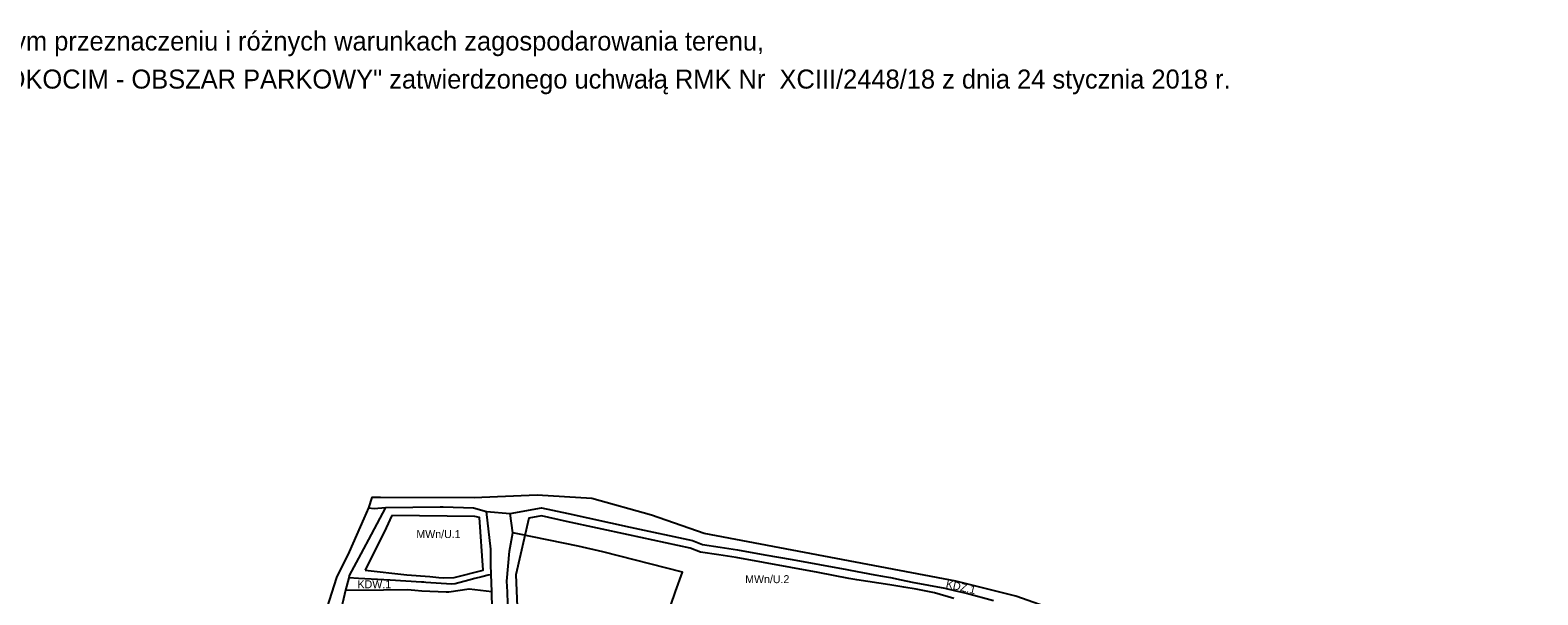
# Model space of a CAD drawing. Extents: x 7427219 to 7428976, y 5542673 to 5543767.
# Drawn here: x 7428025 to 7428976, y 5543411 to 5543767 of the extents above; entities that cross this region are included whole.
import ezdxf

# ---------------------------------------------------------------- set-up
doc = ezdxf.new("R2010")
doc.units = 0
for name, color, linetype in [('info', 7, 'Continuous'), ('linie rozgraniczające', 7, 'Continuous'), ('nieprzekraczalne linie zabudowy', 7, 'Continuous'), ('przeznaczenia terenów', 7, 'Continuous')]:
    doc.layers.add(name, color=color, linetype=linetype)

msp = doc.modelspace()

# ---------------------------------------------------------------- linework, layer by layer
at = {"layer": 'linie rozgraniczające'}
for points in [[(7428955.18, 5543269.67), (7428957.17, 5543269.08), (7428958.88, 5543268.54), (7428976.29, 5543277.15), (7428968.53, 5543280.57), (7428960.48, 5543282.86), (7428942.01, 5543289.47), (7428800.87, 5543352.36), (7428797.41, 5543343.78), (7428792.41, 5543346.08), (7428699.97, 5543390.65), (7428672.76, 5543400.83), (7428647, 5543409.84), (7428609.24, 5543419.25), (7428450.4, 5543449.31), (7428417.15, 5543461.01), (7428379.61, 5543471.46), (7428345.06, 5543473.61), (7428320.11, 5543472.52), (7428305.29, 5543471.75), (7428246.28, 5543471.97), (7428240.89, 5543471.99), (7428238.59, 5543465.57)], [(7428238.59, 5543465.57), (7428235.77, 5543458.71), (7428226.52, 5543437.77), (7428218.51, 5543421.58), (7428212.42, 5543402.38), (7428207.49, 5543383.26), (7428202.68, 5543363.59), (7428201.56, 5543343.87), (7428200.64, 5543323.96), (7428195.5, 5543304.35), (7428194.6, 5543302.15), (7428192.06, 5543294.17), (7428191.09, 5543292), (7428191.23, 5543284.94), (7428191.84, 5543269.96), (7428192.23, 5543264.28), (7428193.91, 5543244.78), (7428194.56, 5543235.45), (7428190.78, 5543234.89), (7428194.45, 5543220.26)], [(7428249.39, 5543465.75), (7428240.39, 5543448.79), (7428233.79, 5543436.58), (7428226.41, 5543422.9), (7428226.33, 5543421.38)], [(7428238.59, 5543465.57), (7428242.19, 5543465.16), (7428249.39, 5543465.75)], [(7428249.39, 5543465.75), (7428283.84, 5543466.14), (7428285.71, 5543466.08), (7428304.82, 5543465.56), (7428313.2, 5543463.31)], [(7428313.2, 5543463.31), (7428328.1, 5543461.86)], [(7428316.03, 5543423.42), (7428315.76, 5543429.79), (7428315.9, 5543438.71), (7428315.92, 5543439.4), (7428313.2, 5543463.31)], [(7428328.1, 5543461.86), (7428347.87, 5543465.51), (7428364.61, 5543461.88), (7428403.83, 5543453.36), (7428443.06, 5543444.83), (7428449.39, 5543442.51), (7428460.45, 5543440.81), (7428471.5, 5543439.11), (7428488.71, 5543435.99), (7428505.93, 5543432.86), (7428523.15, 5543429.74), (7428540.37, 5543426.61), (7428542.42, 5543426.2), (7428550.27, 5543424.76), (7428558.11, 5543423.32), (7428563, 5543422.45), (7428567.88, 5543421.58), (7428574.75, 5543420.12), (7428581.61, 5543418.65), (7428602.14, 5543414.85), (7428609.07, 5543413.25), (7428616, 5543411.66), (7428632.9, 5543406.99)], [(7428329.67, 5543449.79), (7428328.1, 5543461.86)], [(7428321.94, 5543244.46), (7428323.04, 5543250.26), (7428323.58, 5543267.97), (7428324.39, 5543280.12), (7428324.8, 5543286.26), (7428324.9, 5543291.59), (7428325.18, 5543294.57), (7428326.3, 5543306.46), (7428326.5, 5543316.1), (7428327.45, 5543338.07), (7428327.66, 5543360.9), (7428328.46, 5543379.09), (7428327.48, 5543394.39), (7428327.29, 5543397.44), (7428326.66, 5543404.98), (7428326.33, 5543412.61), (7428326.05, 5543419.3), (7428327.63, 5543438.11), (7428329.67, 5543449.79)], [(7428424.62, 5543379.08), (7428421.31, 5543380.22), (7428423.65, 5543387.36), (7428426.35, 5543395.61), (7428432.35, 5543412.79), (7428436.73, 5543424.89), (7428386.45, 5543437.69), (7428371, 5543441.36), (7428332.9, 5543449.13), (7428329.67, 5543449.79)], [(7428226.33, 5543421.38), (7428224.13, 5543413.63)], [(7428316.03, 5543423.42), (7428315.69, 5543423.33), (7428314.23, 5543422.97), (7428310.08, 5543421.94), (7428305.85, 5543420.89), (7428301.89, 5543419.85), (7428293.31, 5543417.59), (7428290.95, 5543417.38), (7428274.96, 5543418.45), (7428273.61, 5543418.6), (7428272.2, 5543418.75), (7428252.26, 5543419.89), (7428232.32, 5543421.03), (7428226.33, 5543421.38)], [(7428316.48, 5543412.76), (7428316.03, 5543423.42)], [(7428224.13, 5543413.63), (7428220.2, 5543396.4), (7428218.9, 5543395.88), (7428212.9, 5543375.79), (7428210.05, 5543366.97), (7428208.01, 5543350.56), (7428210.59, 5543325.44), (7428211.45, 5543313.62)], [(7428224.13, 5543413.63), (7428248.11, 5543413.83), (7428263.25, 5543414.07), (7428268, 5543413.51), (7428272.28, 5543413.15), (7428287.6, 5543412.55), (7428289.31, 5543412.48), (7428302.23, 5543414.39), (7428316.48, 5543412.76)], [(7428317.48, 5543350.67), (7428317.01, 5543369.34), (7428316.88, 5543379.9), (7428316.75, 5543390.46), (7428316.62, 5543401.61), (7428316.48, 5543412.76)]]:
    msp.add_lwpolyline(points, dxfattribs=at)
at = {"layer": 'nieprzekraczalne linie zabudowy'}
for points in [[(7428253.4, 5543460.61), (7428249.86, 5543452.95), (7428236.66, 5543426.14)], [(7428236.66, 5543426.14), (7428262.9, 5543423.24), (7428277.42, 5543422.14), (7428282.99, 5543421.51), (7428285.84, 5543421.45), (7428292.63, 5543421.5), (7428310.99, 5543426.24), (7428308.62, 5543459.36), (7428305.71, 5543460.14), (7428253.4, 5543460.61)], [(7428607.95, 5543408.38), (7428595.68, 5543411.9), (7428584.13, 5543414.23), (7428576.36, 5543415.49), (7428567.56, 5543416.93), (7428546.77, 5543420.14), (7428541.59, 5543421), (7428522.26, 5543424.82), (7428505.04, 5543427.94), (7428487.82, 5543431.07), (7428470.67, 5543434.18), (7428459.69, 5543435.87), (7428448.14, 5543437.64), (7428441.66, 5543440.02), (7428402.77, 5543448.47), (7428363.55, 5543456.99), (7428347.79, 5543460.41), (7428339.87, 5543458.95), (7428331.65, 5543423.21), (7428333.42, 5543378.1)]]:
    msp.add_lwpolyline(points, dxfattribs=at)

# ---------------------------------------------------------------- texts
at = {"layer": 'info'}
for s, p in [('Materiał pomocniczy zawierający linie rozgraniczające teren o różnym przeznaczeniu i różnych warunkach zagospodarowania terenu, ', (7427540.11, 5543753.93)), ('opracowane w skali 1:1000 pochodzące z Miejscowego Planu Zagospodarowania Przestrzennego obszaru "PROKOCIM - OBSZAR PARKOWY" zatwierdzonego uchwałą RMK Nr  XCIII/2448/18 z dnia 24 stycznia 2018 r.', (7427218.26, 5543729.93))]:
    msp.add_text(s, height=12, dxfattribs=at).set_placement(p)
at = {"layer": 'przeznaczenia terenów'}
for s, p in [('MWn/U.1', (7428268.91, 5543446.47)), ('KDW.1', (7428231.79, 5543414.81)), ('MWn/U.2', (7428476.3, 5543418.05))]:
    msp.add_text(s, height=5, dxfattribs=at).set_placement(p)
msp.add_text('KDZ.1', height=5, rotation=347.13523, dxfattribs=at).set_placement((7428602.58, 5543415.32))

doc.saveas('drawing.dxf')
